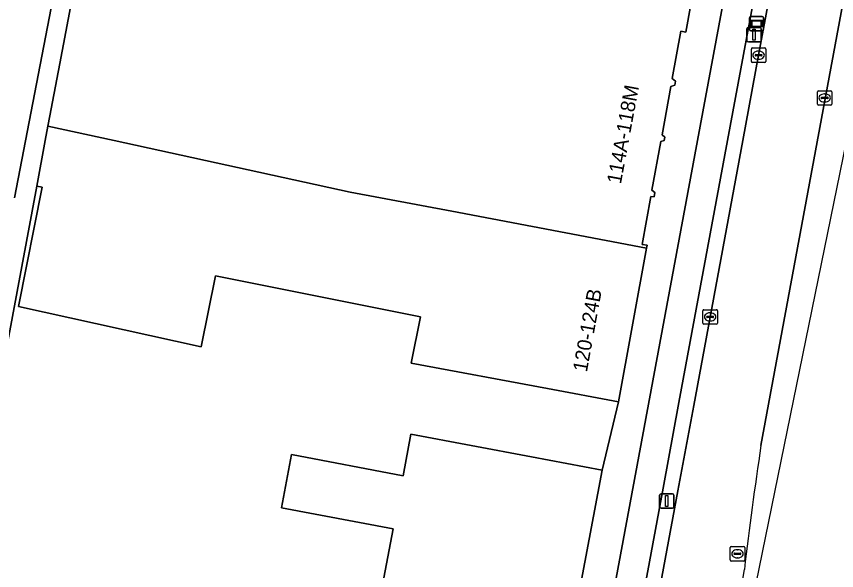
# Model space of a CAD drawing. Extents: x 161402 to 161933, y 381647 to 382315.
# Drawn here: x 161804.7 to 161861.6, y 381720.2 to 381758.6 of the extents above; entities that cross this region are included whole.
import ezdxf

# ---------------------------------------------------------------- set-up
doc = ezdxf.new("R2010")
doc.units = 0
for name, color, linetype in [('IMGEO_Berm_open', 7, 'Continuous'), ('IMGEO_Erf', 7, 'Continuous'), ('IMGEO_Fietspad_gesloten', 7, 'Continuous'), ('IMGEO_Kolk', 7, 'Continuous'), ('IMGEO_Lichtmast', 7, 'Continuous'), ('IMGEO_OVBaan_gesloten', 7, 'Continuous'), ('IMGEO_Pand', 7, 'Continuous'), ('IMGEO_Pand_nummerreeks', 7, 'Continuous'), ('IMGEO_Rijbaan_lokaal_gesloten', 7, 'Continuous'), ('IMGEO_Rioolput', 7, 'Continuous'), ('IMGEO_Voetpad_open', 7, 'Continuous'), ('IMGEO_Wegwijzer', 7, 'Continuous')]:
    doc.layers.add(name, color=color, linetype=linetype)

msp = doc.modelspace()

# ---------------------------------------------------------------- linework, layer by layer
at = {"layer": 'IMGEO_Berm_open'}
for points in [[(161855.069, 381750), (161856.164, 381755.911), (161857.682, 381764.091), (161858.781, 381770.01), (161859.554, 381774.178), (161860.503, 381779.34), (161860.529, 381779.475), (161865.316, 381804.498), (161864.254, 381804.698), (161859.509, 381779.56), (161854.016, 381750), (161850.643, 381731.85), (161849.541, 381725.922), (161844.249, 381697.445)], [(161840.392, 381675.483), (161840.43, 381675.643), (161841.162, 381678.679), (161841.621, 381680.659), (161841.891, 381681.821), (161845.077, 381696.29), (161845.656, 381699.227), (161845.879, 381700.449), (161850.569, 381725.731), (161851.669, 381731.66), (161855.069, 381750)]]:
    msp.add_lwpolyline(points, dxfattribs=at)
at = {"layer": 'IMGEO_Erf'}
for points in [[(161804.575, 381746.036), (161807.111, 381759.198), (161793.961, 381762.994)], [(161827.019, 381703.087), (161830.821, 381723.103), (161823.085, 381724.572), (161823.785, 381728.257), (161831.52, 381726.788), (161832.066, 381729.665), (161840.41, 381728.097), (161845.322, 381727.164), (161846.453, 381731.901), (161841.538, 381732.82), (161832.077, 381734.588), (161832.719, 381737.797), (161818.513, 381740.64), (161817.529, 381735.723), (161804.849, 381738.517), (161806.502, 381746.774), (161806.126, 381746.844), (161801.301, 381721.11)]]:
    msp.add_lwpolyline(points, dxfattribs=at)
at = {"layer": 'IMGEO_Fietspad_gesloten'}
for points in [[(161910.061, 382061.001), (161905.702, 382037.375), (161898.752, 382000), (161887.89, 381941.593), (161886.669, 381935.154), (161880.56, 381902.497), (161879.486, 381896.758), (161857.65, 381780.798), (161851.928, 381750), (161842.232, 381697.819)], [(161844.249, 381697.445), (161849.541, 381725.922), (161850.643, 381731.85), (161854.016, 381750), (161859.509, 381779.56), (161864.254, 381804.698), (161864.714, 381807.133), (161867.323, 381820.954), (161867.824, 381823.608), (161869.899, 381834.602), (161881.54, 381896.271)]]:
    msp.add_lwpolyline(points, dxfattribs=at)
at = {"layer": 'IMGEO_Kolk'}
for p, q in [((161855.661, 381755.485), (161855.661, 381756.337)), ((161855.736, 381756.411), (161856.588, 381756.411)), ((161856.149, 381756.191), (161856.174, 381756.191)), ((161856.662, 381756.337), (161856.662, 381755.485)), ((161855.92, 381755.905), (161855.92, 381755.917)), ((161856.358, 381755.868), (161855.96, 381755.868)), ((161855.963, 381755.954), (161856.361, 381755.954)), ((161856.172, 381755.631), (161856.147, 381755.631)), ((161856.404, 381755.917), (161856.404, 381755.905)), ((161856.588, 381755.411), (161855.736, 381755.411)), ((161852.304, 381737.36), (161852.304, 381738.212)), ((161852.379, 381738.286), (161853.231, 381738.286)), ((161852.792, 381738.066), (161852.817, 381738.066)), ((161853.305, 381738.212), (161853.305, 381737.36)), ((161852.563, 381737.78), (161852.563, 381737.792)), ((161853.001, 381737.743), (161852.603, 381737.743)), ((161852.606, 381737.829), (161853.004, 381737.829)), ((161852.815, 381737.506), (161852.79, 381737.506)), ((161853.047, 381737.792), (161853.047, 381737.78)), ((161853.231, 381737.286), (161852.379, 381737.286))]:
    msp.add_line(p, q, dxfattribs=at)
for points in [[(161855.661, 381755.485), (161855.661, 381756.337)], [(161855.736, 381756.411), (161856.588, 381756.411)], [(161856.662, 381756.337), (161856.662, 381755.485)], [(161856.588, 381755.411), (161855.736, 381755.411)], [(161852.304, 381737.36), (161852.304, 381738.212)], [(161852.379, 381738.286), (161853.231, 381738.286)], [(161853.305, 381738.212), (161853.305, 381737.36)], [(161853.231, 381737.286), (161852.379, 381737.286)]]:
    msp.add_lwpolyline(points, dxfattribs=at)
for centre, radius, start, end in [((161855.738, 381756.335), 0.0765, 91.552, 178.448), ((161855.738, 381756.335), 0.0765, 91.552, 178.448), ((161856.586, 381756.335), 0.0765, 1.552, 88.448), ((161856.586, 381756.335), 0.0765, 1.552, 88.448), ((161855.96, 381755.914), 0.0403, 85.8775, 175.7526), ((161855.957, 381755.904), 0.0366, 178.938, 274.7102), ((161856.361, 381755.911), 0.043, 264.8664, 352.4533), ((161856.365, 381755.916), 0.0386, 1.7309, 96.639), ((161855.738, 381755.487), 0.0765, 181.552, 268.448), ((161855.738, 381755.487), 0.0765, 181.552, 268.448), ((161856.586, 381755.487), 0.0765, 271.552, 358.448), ((161856.586, 381755.487), 0.0765, 271.552, 358.448), ((161852.381, 381738.21), 0.0765, 91.552, 178.448), ((161852.381, 381738.21), 0.0765, 91.552, 178.448), ((161853.229, 381738.21), 0.0765, 1.552, 88.448), ((161853.229, 381738.21), 0.0765, 1.552, 88.448), ((161852.381, 381737.362), 0.0765, 181.552, 268.448), ((161852.381, 381737.362), 0.0765, 181.552, 268.448), ((161852.603, 381737.789), 0.0403, 85.8775, 175.7526), ((161852.6, 381737.779), 0.0366, 178.938, 274.7102), ((161853.004, 381737.786), 0.043, 264.8664, 352.4533), ((161853.008, 381737.791), 0.0386, 1.7309, 96.639), ((161853.229, 381737.362), 0.0765, 271.552, 358.448), ((161853.229, 381737.362), 0.0765, 271.552, 358.448)]:
    msp.add_arc(centre, radius, start, end, dxfattribs=at)
for centre, major_axis, ratio, start_param, end_param in [((161856.148, 381755.911), (-0.387, 0.002), 0.722429, 4.712389, 7.853982), ((161856.173, 381755.911), (-0.39, 0.002), 0.717154, 1.570796, 4.712389), ((161852.791, 381737.786), (-0.387, 0.002), 0.722429, 4.712389, 7.853982), ((161852.816, 381737.786), (-0.39, 0.002), 0.717154, 1.570796, 4.712389)]:
    msp.add_ellipse(centre, major_axis=major_axis, ratio=ratio, start_param=start_param, end_param=end_param, dxfattribs=at)
at = {"layer": 'IMGEO_Lichtmast'}
for p, q in [((161855.454, 381757.836), (161856.244, 381757.836)), ((161856.244, 381757.836), (161855.454, 381757.836)), ((161855.354, 381756.936), (161855.354, 381757.736)), ((161855.354, 381757.736), (161855.354, 381756.936)), ((161856.344, 381757.736), (161856.344, 381756.936)), ((161856.344, 381756.936), (161856.344, 381757.736)), ((161856.244, 381756.836), (161855.454, 381756.836)), ((161855.454, 381756.836), (161856.244, 381756.836)), ((161849.302, 381724.631), (161849.302, 381725.431)), ((161849.302, 381725.431), (161849.302, 381724.631)), ((161849.402, 381725.531), (161850.192, 381725.531)), ((161850.192, 381725.531), (161849.402, 381725.531)), ((161850.292, 381725.431), (161850.292, 381724.631)), ((161850.292, 381724.631), (161850.292, 381725.431)), ((161850.192, 381724.531), (161849.402, 381724.531)), ((161849.402, 381724.531), (161850.192, 381724.531))]:
    msp.add_line(p, q, dxfattribs=at)
for points in [[(161855.774, 381757.711), (161855.924, 381757.711), (161855.924, 381756.961), (161855.774, 381756.961), (161855.774, 381757.711)], [(161849.722, 381725.406), (161849.872, 381725.406), (161849.872, 381724.656), (161849.722, 381724.656), (161849.722, 381725.406)]]:
    msp.add_lwpolyline(points, dxfattribs=at)
for centre, start, end in [((161855.454, 381757.736), 90, 180), ((161855.454, 381757.736), 90, 180), ((161856.244, 381757.736), 0, 90), ((161856.244, 381757.736), 360, 90), ((161855.454, 381756.936), 180, 270), ((161855.454, 381756.936), 180, 270), ((161856.244, 381756.936), 270, 0), ((161856.244, 381756.936), 270, 0), ((161849.402, 381725.431), 90, 180), ((161849.402, 381725.431), 90, 180), ((161850.192, 381725.431), 0, 90), ((161850.192, 381725.431), 360, 90), ((161849.402, 381724.631), 180, 270), ((161849.402, 381724.631), 180, 270), ((161850.192, 381724.631), 270, 0), ((161850.192, 381724.631), 270, 0)]:
    msp.add_arc(centre, 0.1, start, end, dxfattribs=at)
at = {"layer": 'IMGEO_OVBaan_gesloten'}
for points in [[(161847.327, 381677.629), (161847.814, 381679.325), (161869.795, 381786.79), (161883.773, 381866.122), (161911.481, 382007.357), (161916.93, 382035.129), (161933.101, 382124.399), (161931.462, 382125.963), (161930.949, 382121.39)], [(161929.574, 382113.249), (161927.659, 382104.365), (161926.989, 382101.276), (161926.695, 382099.95), (161920.797, 382074.121), (161920.568, 382072.989), (161920.066, 382070.485), (161894.174, 381930.698), (161894.155, 381930.593), (161893.956, 381929.536), (161893.492, 381927.072), (161889.963, 381908.334), (161866.208, 381782.197), (161866.199, 381782.149), (161865.069, 381776.053), (161864.537, 381773.18), (161864.311, 381771.961), (161856.328, 381728.885)]]:
    msp.add_lwpolyline(points, dxfattribs=at)
for centre, radius, start, end in [((162161.953, 381683.521), 308.973, 171.55727, 173.16432), ((161499.286, 381771.682), 359.581, 349.05687, 351.78402)]:
    msp.add_arc(centre, radius, start, end, dxfattribs=at)
at = {"layer": 'IMGEO_Pand'}
msp.add_lwpolyline([(161809.872, 381766.703), (161807.718, 381755.345), (161806.917, 381751.12), (161806.895, 381751.005), (161811.485, 381750), (161827.854, 381746.416), (161834.903, 381745.106), (161848.392, 381742.544), (161848.429, 381742.746), (161848.083, 381742.809), (161848.69, 381746.136), (161848.917, 381746.094), (161848.973, 381746.394), (161848.769, 381746.569), (161849.381, 381749.923), (161849.61, 381750), (161849.655, 381750.236), (161849.468, 381750.399), (161850.08, 381753.751), (161850.348, 381753.845), (161850.4, 381754.115), (161850.181, 381754.306), (161850.777, 381757.569), (161851.119, 381757.504), (161851.467, 381759.416)], dxfattribs=at)
for points in [[(161848.392, 381742.544), (161834.903, 381745.106), (161827.854, 381746.416), (161811.485, 381750), (161806.895, 381751.005), (161806.71, 381750), (161806.126, 381746.844), (161806.502, 381746.774), (161804.849, 381738.517), (161817.529, 381735.723), (161818.513, 381740.64), (161832.719, 381737.797), (161832.077, 381734.588), (161841.538, 381732.82), (161846.453, 381731.901)], [(161826.668, 381693.365), (161836.743, 381691.565), (161838.428, 381700.436), (161840.209, 381700.098), (161845.322, 381727.164), (161840.41, 381728.097), (161832.066, 381729.665), (161831.52, 381726.788), (161823.785, 381728.257), (161823.085, 381724.572), (161830.821, 381723.103), (161827.019, 381703.087), (161825.224, 381703.428), (161824.188, 381697.974), (161821.755, 381698.436), (161820.996, 381694.433)]]:
    msp.add_lwpolyline(points, close=True, dxfattribs=at)
at = {"layer": 'IMGEO_Rijbaan_lokaal_gesloten'}
for points in [[(161884.17, 381893.607), (161884.15, 381893.504), (161864.093, 381787.863), (161863.613, 381786.178), (161863.081, 381785.029), (161862.376, 381783.945), (161861.521, 381781.789), (161860.529, 381779.475), (161860.503, 381779.34), (161859.554, 381774.178), (161858.781, 381770.01), (161857.682, 381764.091), (161856.164, 381755.911), (161855.069, 381750), (161851.669, 381731.66), (161850.569, 381725.731), (161845.879, 381700.449), (161845.656, 381699.227), (161845.077, 381696.29), (161841.891, 381681.821), (161841.621, 381680.659), (161841.162, 381678.679), (161840.43, 381675.643), (161840.392, 381675.483)], [(161856.328, 381728.885), (161864.311, 381771.961)]]:
    msp.add_lwpolyline(points, dxfattribs=at)
for centre, radius, start, end in [((162161.953, 381683.521), 308.973, 171.55727, 173.16432), ((161499.286, 381771.682), 359.581, 349.05687, 351.78402)]:
    msp.add_arc(centre, radius, start, end, dxfattribs=at)
at = {"layer": 'IMGEO_Rioolput'}
for p, q in [((161860.244, 381752.526), (161860.244, 381753.378)), ((161860.319, 381753.452), (161861.171, 381753.452)), ((161861.245, 381753.378), (161861.245, 381752.526)), ((161860.503, 381752.946), (161860.503, 381752.958)), ((161860.941, 381752.909), (161860.543, 381752.909)), ((161860.546, 381752.995), (161860.944, 381752.995)), ((161860.732, 381753.232), (161860.757, 381753.232)), ((161860.987, 381752.958), (161860.987, 381752.946)), ((161861.171, 381752.452), (161860.319, 381752.452)), ((161860.755, 381752.672), (161860.73, 381752.672)), ((161854.199, 381720.952), (161854.199, 381721.804)), ((161854.274, 381721.878), (161855.126, 381721.878)), ((161854.687, 381721.658), (161854.712, 381721.658)), ((161855.2, 381721.804), (161855.2, 381720.952)), ((161855.126, 381720.878), (161854.274, 381720.878)), ((161854.458, 381721.372), (161854.458, 381721.384)), ((161854.896, 381721.335), (161854.498, 381721.335)), ((161854.501, 381721.421), (161854.899, 381721.421)), ((161854.71, 381721.098), (161854.685, 381721.098)), ((161854.942, 381721.384), (161854.942, 381721.372))]:
    msp.add_line(p, q, dxfattribs=at)
for points in [[(161860.244, 381752.526), (161860.244, 381753.378)], [(161860.319, 381753.452), (161861.171, 381753.452)], [(161861.245, 381753.378), (161861.245, 381752.526)], [(161861.171, 381752.452), (161860.319, 381752.452)], [(161854.199, 381720.952), (161854.199, 381721.804)], [(161854.274, 381721.878), (161855.126, 381721.878)], [(161855.2, 381721.804), (161855.2, 381720.952)], [(161855.126, 381720.878), (161854.274, 381720.878)]]:
    msp.add_lwpolyline(points, dxfattribs=at)
for centre, radius, start, end in [((161860.321, 381753.376), 0.0765, 91.552, 178.448), ((161860.321, 381753.376), 0.0765, 91.552, 178.448), ((161861.169, 381753.376), 0.0765, 1.552, 88.448), ((161861.169, 381753.376), 0.0765, 1.552, 88.448), ((161860.543, 381752.955), 0.0403, 85.8775, 175.7526), ((161860.54, 381752.945), 0.0366, 178.938, 274.7102), ((161860.944, 381752.952), 0.043, 264.8664, 352.4533), ((161860.948, 381752.957), 0.0386, 1.7309, 96.639), ((161860.321, 381752.528), 0.0765, 181.552, 268.448), ((161860.321, 381752.528), 0.0765, 181.552, 268.448), ((161861.169, 381752.528), 0.0765, 271.552, 358.448), ((161861.169, 381752.528), 0.0765, 271.552, 358.448), ((161854.276, 381721.802), 0.0765, 91.552, 178.448), ((161854.276, 381721.802), 0.0765, 91.552, 178.448), ((161855.124, 381721.802), 0.0765, 1.552, 88.448), ((161855.124, 381721.802), 0.0765, 1.552, 88.448), ((161854.276, 381720.954), 0.0765, 181.552, 268.448), ((161854.276, 381720.954), 0.0765, 181.552, 268.448), ((161854.498, 381721.381), 0.0403, 85.8775, 175.7526), ((161854.495, 381721.371), 0.0366, 178.938, 274.7102), ((161854.899, 381721.378), 0.043, 264.8664, 352.4533), ((161854.903, 381721.383), 0.0386, 1.7309, 96.639), ((161855.124, 381720.954), 0.0765, 271.552, 358.448), ((161855.124, 381720.954), 0.0765, 271.552, 358.448)]:
    msp.add_arc(centre, radius, start, end, dxfattribs=at)
for centre, major_axis, ratio, start_param, end_param in [((161860.731, 381752.952), (-0.387, 0.002), 0.722429, 4.712389, 7.853982), ((161860.756, 381752.952), (-0.39, 0.002), 0.717154, 1.570796, 4.712389), ((161854.686, 381721.378), (-0.387, 0.002), 0.722429, 4.712389, 7.853982), ((161854.711, 381721.378), (-0.39, 0.002), 0.717154, 1.570796, 4.712389)]:
    msp.add_ellipse(centre, major_axis=major_axis, ratio=ratio, start_param=start_param, end_param=end_param, dxfattribs=at)
at = {"layer": 'IMGEO_Voetpad_open'}
for points in [[(161842.232, 381697.819), (161851.928, 381750), (161857.65, 381780.798), (161879.486, 381896.758)], [(161801.301, 381721.11), (161806.126, 381746.844), (161806.71, 381750), (161806.895, 381751.005), (161806.917, 381751.12), (161807.718, 381755.345), (161809.872, 381766.703), (161809.949, 381766.688), (161810.222, 381768.128), (161810.816, 381771.077), (161811.409, 381773.853), (161814.104, 381788.412), (161814.041, 381788.423), (161814.532, 381791.116), (161814.602, 381791.103), (161814.613, 381791.164), (161820.446, 381819.524)], [(161793.961, 381762.994), (161807.111, 381759.198), (161804.575, 381746.036)], [(161851.467, 381759.416), (161851.119, 381757.504), (161850.777, 381757.569), (161850.181, 381754.306), (161850.4, 381754.115), (161850.348, 381753.845), (161850.08, 381753.751), (161849.468, 381750.399), (161849.655, 381750.236), (161849.61, 381750), (161849.381, 381749.923), (161848.769, 381746.569), (161848.973, 381746.394), (161848.917, 381746.094), (161848.69, 381746.136), (161848.083, 381742.809), (161848.429, 381742.746), (161848.392, 381742.544), (161846.453, 381731.901), (161845.322, 381727.164), (161840.209, 381700.098)]]:
    msp.add_lwpolyline(points, dxfattribs=at)
at = {"layer": 'IMGEO_Wegwijzer'}
for p, q in [((161855.523, 381757.698), (161855.523, 381758.498)), ((161855.523, 381758.498), (161855.523, 381757.698)), ((161855.623, 381758.598), (161856.413, 381758.598)), ((161856.413, 381758.598), (161855.623, 381758.598)), ((161856.513, 381758.498), (161856.513, 381757.698)), ((161856.513, 381757.698), (161856.513, 381758.498)), ((161856.413, 381757.598), (161855.623, 381757.598)), ((161855.623, 381757.598), (161856.413, 381757.598))]:
    msp.add_line(p, q, dxfattribs=at)
for points in [[(161855.624, 381758.33), (161856.412, 381758.33), (161856.412, 381757.866), (161855.624, 381757.866), (161855.624, 381758.33)], [(161855.689, 381758.265), (161855.689, 381757.931), (161856.347, 381757.931), (161856.347, 381758.265), (161855.689, 381758.265)]]:
    msp.add_lwpolyline(points, dxfattribs=at)
for centre, start, end in [((161855.623, 381758.498), 90, 180), ((161855.623, 381758.498), 90, 180), ((161856.413, 381758.498), 0, 90), ((161856.413, 381758.498), 360, 90), ((161855.623, 381757.698), 180, 270), ((161855.623, 381757.698), 180, 270), ((161856.413, 381757.698), 270, 0), ((161856.413, 381757.698), 270, 0)]:
    msp.add_arc(centre, 0.1, start, end, dxfattribs=at)

# ---------------------------------------------------------------- texts
at = {"layer": 'IMGEO_Pand_nummerreeks'}
for s, rotation, p in [('114A-118M', 79.4922, (161846.618, 381746.946)), ('120-124B', 79.6755, (161844.26, 381733.922))]:
    msp.add_text(s, height=1, rotation=rotation, dxfattribs=at).set_placement(p)

doc.saveas('drawing.dxf')
